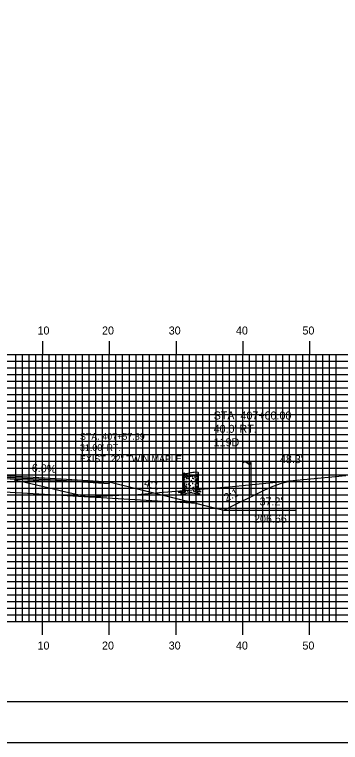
# Model space of a CAD drawing. Extents: x 852529 to 852872, y 364785 to 365005.
# Drawn here: x 852700.5 to 852749.3, y 364785.1 to 364894.2 of the extents above; entities that cross this region are included whole.
import ezdxf

# ---------------------------------------------------------------- set-up
doc = ezdxf.new("R2010")
doc.units = 0
for name, color, linetype in [('ANNOTATION', 7, 'Continuous'), ('BORDER', 7, 'Continuous'), ('D_Drainage_Text', 7, 'Continuous'), ('D_Roadway_Centerline', 7, 'Continuous'), ('D_Roadway_Edge_Shoulder', 7, 'Continuous'), ('D_Roadway_Edge_TW', 7, 'Continuous'), ('D_Roadway_Pavement', 7, 'Continuous'), ('D_Roadway_SlopeLines', 7, 'Continuous'), ('D_Roadway_SubGrade', 7, 'Continuous'), ('D_Text_Monospaced', 7, 'Continuous'), ('D_Text_Standard', 7, 'Continuous'), ('D_Utilities_Pole_Joint', 7, 'Continuous'), ('H_V ANNOTATION', 7, 'Continuous'), ('MAJOR', 7, 'Continuous'), ('MINOR', 7, 'Continuous'), ('PDRAIN', 7, 'Continuous'), ('PLOT BOUNDARY', 7, 'Continuous'), ('S_Roadway_Centerline', 7, 'Continuous'), ('S_Trees_Decid_Pay', 7, 'Continuous')]:
    doc.layers.add(name, color=color, linetype=linetype)

msp = doc.modelspace()

# ---------------------------------------------------------------- linework, layer by layer
at = {"layer": 'BORDER'}
msp.add_lwpolyline([(852545.13, 364791.23), (852865.13, 364791.23), (852865.13, 365001.23), (852545.13, 365001.23)], close=True, dxfattribs=at)
at = {"layer": 'D_Roadway_Centerline'}
msp.add_lwpolyline([(852662.11, 364822.74), (852662.73, 364822.94), (852663.86, 364823.23), (852674.73, 364825.94), (852682.73, 364826.1), (852694.73, 364825.38), (852706.73, 364824.66), (852714.73, 364824.18), (852727.89, 364820.89), (852731.89, 364819.89), (852738.01, 364822.95), (852739.26, 364823.52), (852740.51, 364823.95), (852741.76, 364824.26), (852743.01, 364824.45)], dxfattribs=at)
at = {"layer": 'D_Roadway_Edge_Shoulder'}
msp.add_lwpolyline([(852706.73, 364824.66), (852714.73, 364824.18), (852714.73, 364823.93), (852706.73, 364824.41)], close=True, dxfattribs=at)
at = {"layer": 'D_Roadway_Edge_TW'}
msp.add_lwpolyline([(852682.73, 364825.85), (852682.73, 364826.1), (852694.73, 364825.38), (852706.73, 364824.66), (852706.73, 364824.41), (852694.73, 364825.13)], close=True, dxfattribs=at)
at = {"layer": 'D_Roadway_Pavement'}
msp.add_lwpolyline([(852682.73, 364825.6), (852682.73, 364825.85), (852694.73, 364825.13), (852706.73, 364824.41), (852706.73, 364824.16), (852694.73, 364824.88)], close=True, dxfattribs=at)
at = {"layer": 'D_Roadway_SlopeLines'}
for points in [[(852714.73, 364824.18), (852731.89, 364819.89)], [(852731.89, 364819.89), (852738.01, 364822.95), (852739.26, 364823.52), (852740.51, 364823.95), (852741.76, 364824.26), (852743.01, 364824.45)]]:
    msp.add_lwpolyline(points, dxfattribs=at)
at = {"layer": 'D_Roadway_SubGrade'}
msp.add_lwpolyline([(852682.73, 364823.6), (852663.86, 364823.23), (852674.73, 364825.94), (852674.73, 364825.69), (852682.73, 364825.85), (852694.73, 364825.13), (852706.73, 364824.41), (852714.73, 364823.93), (852714.73, 364824.18), (852727.89, 364820.89), (852706.73, 364822.16), (852694.73, 364822.88)], close=True, dxfattribs=at)
at = {"layer": 'D_Utilities_Pole_Joint'}
for p, q in [((852734.73, 364826.99), (852734.89, 364827.1)), ((852734.73, 364822.23), (852734.73, 364826.99)), ((852735.2, 364827.1), (852735.36, 364826.99)), ((852735.51, 364827.1), (852735.36, 364826.99)), ((852735.36, 364826.99), (852735.51, 364826.88)), ((852735.98, 364826.99), (852735.82, 364827.1)), ((852735.82, 364826.88), (852735.98, 364826.99)), ((852735.98, 364822.23), (852735.98, 364826.99))]:
    msp.add_line(p, q, dxfattribs=at)
for centre, start, end in [((852735.04, 364826.88), 90, 125.2644), ((852735.04, 364826.88), 54.7356, 90), ((852735.67, 364826.88), 90, 125.2644), ((852735.67, 364827.1), 234.7356, 270), ((852735.67, 364826.88), 54.7356, 90), ((852735.67, 364827.1), 270, 305.2644)]:
    msp.add_arc(centre, 0.271, start, end, dxfattribs=at)
at = {"layer": 'MAJOR'}
for p, q in [((852704.73, 364845.24), (852704.73, 364843.23)), ((852714.73, 364845.24), (852714.73, 364843.23)), ((852724.73, 364845.24), (852724.73, 364843.23)), ((852734.73, 364845.24), (852734.73, 364843.23)), ((852744.73, 364845.24), (852744.73, 364843.23)), ((852554.73, 364843.23), (852834.73, 364843.23)), ((852554.73, 364843.23), (852834.73, 364843.23)), ((852704.73, 364803.23), (852704.73, 364843.23)), ((852714.73, 364803.23), (852714.73, 364843.23)), ((852724.73, 364803.23), (852724.73, 364843.23)), ((852734.73, 364803.23), (852734.73, 364843.23)), ((852744.73, 364803.23), (852744.73, 364843.23)), ((852554.73, 364838.23), (852834.73, 364838.23)), ((852554.73, 364833.23), (852834.73, 364833.23)), ((852554.73, 364828.23), (852834.73, 364828.23)), ((852554.73, 364823.23), (852834.73, 364823.23)), ((852554.73, 364818.23), (852834.73, 364818.23)), ((852554.73, 364813.23), (852834.73, 364813.23)), ((852554.73, 364808.23), (852834.73, 364808.23)), ((852554.73, 364803.23), (852834.73, 364803.23)), ((852554.73, 364803.23), (852834.73, 364803.23)), ((852704.73, 364801.23), (852704.73, 364803.23)), ((852714.73, 364801.23), (852714.73, 364803.23)), ((852724.73, 364801.23), (852724.73, 364803.23)), ((852734.73, 364801.23), (852734.73, 364803.23)), ((852744.73, 364801.23), (852744.73, 364803.23))]:
    msp.add_line(p, q, dxfattribs=at)
at = {"layer": 'MINOR'}
for p, q in [((852700.73, 364803.23), (852700.73, 364843.23)), ((852701.73, 364803.23), (852701.73, 364843.23)), ((852702.73, 364803.23), (852702.73, 364843.23)), ((852703.73, 364803.23), (852703.73, 364843.23)), ((852705.73, 364803.23), (852705.73, 364843.23)), ((852706.73, 364803.23), (852706.73, 364843.23)), ((852707.73, 364803.23), (852707.73, 364843.23)), ((852708.73, 364803.23), (852708.73, 364843.23)), ((852709.73, 364803.23), (852709.73, 364843.23)), ((852710.73, 364803.23), (852710.73, 364843.23)), ((852711.73, 364803.23), (852711.73, 364843.23)), ((852712.73, 364803.23), (852712.73, 364843.23)), ((852713.73, 364803.23), (852713.73, 364843.23)), ((852715.73, 364803.23), (852715.73, 364843.23)), ((852716.73, 364803.23), (852716.73, 364843.23)), ((852717.73, 364803.23), (852717.73, 364843.23)), ((852718.73, 364803.23), (852718.73, 364843.23)), ((852719.73, 364803.23), (852719.73, 364843.23)), ((852720.73, 364803.23), (852720.73, 364843.23)), ((852721.73, 364803.23), (852721.73, 364843.23)), ((852722.73, 364803.23), (852722.73, 364843.23)), ((852723.73, 364803.23), (852723.73, 364843.23)), ((852725.73, 364803.23), (852725.73, 364843.23)), ((852726.73, 364803.23), (852726.73, 364843.23)), ((852727.73, 364803.23), (852727.73, 364843.23)), ((852728.73, 364803.23), (852728.73, 364843.23)), ((852729.73, 364803.23), (852729.73, 364843.23)), ((852730.73, 364803.23), (852730.73, 364843.23)), ((852731.73, 364803.23), (852731.73, 364843.23)), ((852732.73, 364803.23), (852732.73, 364843.23)), ((852733.73, 364803.23), (852733.73, 364843.23)), ((852735.73, 364803.23), (852735.73, 364843.23)), ((852736.73, 364803.23), (852736.73, 364843.23)), ((852737.73, 364803.23), (852737.73, 364843.23)), ((852738.73, 364803.23), (852738.73, 364843.23)), ((852739.73, 364803.23), (852739.73, 364843.23)), ((852740.73, 364803.23), (852740.73, 364843.23)), ((852741.73, 364803.23), (852741.73, 364843.23)), ((852742.73, 364803.23), (852742.73, 364843.23)), ((852743.73, 364803.23), (852743.73, 364843.23)), ((852745.73, 364803.23), (852745.73, 364843.23)), ((852746.73, 364803.23), (852746.73, 364843.23)), ((852747.73, 364803.23), (852747.73, 364843.23)), ((852748.73, 364803.23), (852748.73, 364843.23)), ((852554.73, 364842.23), (852834.73, 364842.23)), ((852554.73, 364841.23), (852834.73, 364841.23)), ((852554.73, 364840.23), (852834.73, 364840.23)), ((852554.73, 364839.23), (852834.73, 364839.23)), ((852554.73, 364837.23), (852834.73, 364837.23)), ((852554.73, 364836.23), (852834.73, 364836.23)), ((852554.73, 364835.23), (852834.73, 364835.23)), ((852554.73, 364834.23), (852834.73, 364834.23)), ((852554.73, 364832.23), (852834.73, 364832.23)), ((852554.73, 364831.23), (852834.73, 364831.23)), ((852554.73, 364830.23), (852834.73, 364830.23)), ((852554.73, 364829.23), (852834.73, 364829.23)), ((852554.73, 364827.23), (852834.73, 364827.23)), ((852554.73, 364826.23), (852834.73, 364826.23)), ((852554.73, 364825.23), (852834.73, 364825.23)), ((852554.73, 364824.23), (852834.73, 364824.23)), ((852554.73, 364822.23), (852834.73, 364822.23)), ((852554.73, 364821.23), (852834.73, 364821.23)), ((852554.73, 364820.23), (852834.73, 364820.23)), ((852554.73, 364819.23), (852834.73, 364819.23)), ((852554.73, 364817.23), (852834.73, 364817.23)), ((852554.73, 364816.23), (852834.73, 364816.23)), ((852554.73, 364815.23), (852834.73, 364815.23)), ((852554.73, 364814.23), (852834.73, 364814.23)), ((852554.73, 364812.23), (852834.73, 364812.23)), ((852554.73, 364811.23), (852834.73, 364811.23)), ((852554.73, 364810.23), (852834.73, 364810.23)), ((852554.73, 364809.23), (852834.73, 364809.23)), ((852554.73, 364807.23), (852834.73, 364807.23)), ((852554.73, 364806.23), (852834.73, 364806.23)), ((852554.73, 364805.23), (852834.73, 364805.23)), ((852554.73, 364804.23), (852834.73, 364804.23))]:
    msp.add_line(p, q, dxfattribs=at)
at = {"layer": 'PDRAIN'}
msp.add_line((852731.89, 364819.89), (852742.66, 364819.89), dxfattribs=at)
at = {"layer": 'PLOT BOUNDARY'}
msp.add_lwpolyline([(852528.94, 364785.11), (852868.94, 364785.11), (852868.94, 365005.11), (852528.94, 365005.11)], close=True, dxfattribs=at)
at = {"layer": 'S_Roadway_Centerline'}
msp.add_lwpolyline([(852700.53, 364824.42), (852700.84, 364824.39), (852701.48, 364824.25), (852703.84, 364823.7), (852706.57, 364823.06), (852707.59, 364822.82), (852711.32, 364821.95), (852712.8, 364822.03), (852713.46, 364822.03), (852717.04, 364822.19), (852717.68, 364822.2), (852718.98, 364822.24), (852721.06, 364822.45), (852733.19, 364823.47), (852735.15, 364823.68), (852743.83, 364824.53), (852750.15, 364825.09)], dxfattribs=at)
at = {"layer": 'S_Trees_Decid_Pay'}
for p, q in [((852725.93, 364825.18), (852725.93, 364825)), ((852727.19, 364825.07), (852727.19, 364824.79)), ((852727.57, 364825.17), (852727.57, 364825.08)), ((852727.84, 364825.08), (852727.84, 364824.89)), ((852727.97, 364825.34), (852727.97, 364825.08)), ((852728.05, 364825.38), (852728.05, 364825.26)), ((852728.05, 364825.21), (852728.05, 364824.99)), ((852725.78, 364824.98), (852725.78, 364824.72)), ((852725.78, 364824.62), (852725.78, 364824.16)), ((852725.78, 364824.1), (852725.78, 364823.97)), ((852725.87, 364824.83), (852725.87, 364824.62)), ((852725.87, 364824.55), (852725.87, 364824.41)), ((852725.87, 364824.23), (852725.87, 364823.93)), ((852726.01, 364824.93), (852726.01, 364824.72)), ((852726.01, 364824.52), (852726.01, 364824.36)), ((852726.01, 364824), (852726.01, 364823.78)), ((852726.28, 364824.93), (852726.28, 364824.81)), ((852726.28, 364824.76), (852726.28, 364824.57)), ((852726.28, 364824.29), (852726.28, 364824.06)), ((852726.51, 364824.66), (852726.52, 364824.77)), ((852726.64, 364824.83), (852726.64, 364824.65)), ((852727.19, 364824.72), (852727.19, 364824.62)), ((852727.19, 364824.01), (852727.19, 364823.79)), ((852727.57, 364824.94), (852727.57, 364824.8)), ((852727.57, 364824.52), (852727.57, 364824.32)), ((852727.84, 364824.64), (852727.84, 364824.36)), ((852727.84, 364824.32), (852727.84, 364824.21)), ((852727.84, 364824.07), (852727.84, 364823.84)), ((852727.97, 364824.99), (852727.97, 364824.72)), ((852727.97, 364824.62), (852727.97, 364824.32)), ((852727.97, 364824.23), (852727.97, 364824.16)), ((852728.05, 364824.95), (852728.05, 364824.61)), ((852728.05, 364824.49), (852728.05, 364824.13)), ((852728.05, 364824.1), (852728.05, 364823.65)), ((852725.78, 364823.04), (852725.77, 364822.92)), ((852725.78, 364823.91), (852725.78, 364823.59)), ((852725.78, 364823.56), (852725.78, 364823.14)), ((852725.87, 364823.89), (852725.87, 364823.65)), ((852725.87, 364823.54), (852725.87, 364823.4)), ((852725.87, 364823.26), (852725.87, 364823.11)), ((852726.01, 364823.68), (852726.01, 364823.56)), ((852726.01, 364823.41), (852726.01, 364823.31)), ((852726.28, 364823.86), (852726.28, 364823.68)), ((852726.28, 364823.44), (852726.28, 364823.36)), ((852726.28, 364823.29), (852726.28, 364823.11)), ((852726.64, 364823.87), (852726.64, 364823.68)), ((852726.64, 364823.29), (852726.64, 364823.19)), ((852727.19, 364823.29), (852727.19, 364823.11)), ((852727.56, 364823.06), (852727.65, 364822.93)), ((852727.57, 364823.84), (852727.57, 364823.64)), ((852727.57, 364823.52), (852727.57, 364823.32)), ((852727.84, 364823.52), (852727.84, 364823.13)), ((852727.97, 364823.93), (852727.97, 364823.83)), ((852727.97, 364823.78), (852727.97, 364823.42)), ((852727.97, 364823.37), (852727.97, 364823.2)), ((852728.05, 364823.58), (852728.05, 364823.3))]:
    msp.add_line(p, q, dxfattribs=at)
for points in [[(852725.73, 364825.25), (852725.73, 364823.11), (852725.71, 364822.97), (852725.7, 364822.85), (852725.66, 364822.76), (852725.57, 364822.71), (852725.43, 364822.71), (852725.19, 364822.65), (852725.02, 364822.61), (852725.16, 364822.57), (852725.4, 364822.61), (852725.61, 364822.6), (852725.87, 364822.61), (852726, 364822.62), (852726.03, 364822.58), (852726.09, 364822.62), (852725.99, 364822.56), (852725.75, 364822.53), (852725.52, 364822.47), (852725.39, 364822.4), (852725.49, 364822.36), (852725.92, 364822.37), (852726.19, 364822.42), (852726.49, 364822.49), (852726.78, 364822.53), (852726.88, 364822.53), (852726.9, 364822.61), (852726.97, 364822.62), (852727.14, 364822.53), (852727.42, 364822.48), (852727.72, 364822.37), (852728.18, 364822.32), (852728.33, 364822.33), (852727.99, 364822.48), (852727.79, 364822.51), (852727.8, 364822.59), (852728.06, 364822.69), (852728.24, 364822.72), (852728.48, 364822.73), (852728.28, 364822.77), (852728.22, 364822.8), (852728.19, 364822.89), (852728.18, 364823.06), (852728.14, 364823.14), (852728.11, 364823.39), (852728.11, 364825.47)], [(852726.09, 364824.92), (852726.08, 364825.07), (852726.03, 364825.06), (852726.02, 364825.43), (852725.92, 364825.44), (852725.91, 364825.52), (852725.87, 364825.19), (852725.83, 364825.28), (852725.81, 364825.13), (852725.73, 364825.25), (852725.74, 364825.06)], [(852725.73, 364825.25), (852725.78, 364825.27), (852725.8, 364825.34), (852725.85, 364825.36), (852725.88, 364825.29)], [(852726.11, 364825.29), (852726.13, 364825.4), (852726.26, 364825.43), (852726.27, 364825.34)], [(852726.25, 364824.93), (852726.28, 364825.03), (852726.35, 364825.04), (852726.35, 364825.12), (852726.42, 364825.13), (852726.45, 364824.95)], [(852725.85, 364823.04), (852725.84, 364822.92), (852725.76, 364822.82)], [(852726, 364822.62), (852726.01, 364822.8), (852726.08, 364822.94), (852726.07, 364823.04)], [(852726.14, 364823.56), (852726.13, 364823.48), (852726.2, 364823.48), (852726.22, 364823.6)], [(852726.64, 364823.01), (852726.62, 364822.85), (852726.42, 364822.77), (852726.38, 364822.67)], [(852727.2, 364823), (852727.31, 364822.95), (852727.32, 364822.74), (852727.42, 364822.71)], [(852727.68, 364823.65), (852727.68, 364823.73), (852727.67, 364823.79)], [(852727.86, 364823.07), (852727.86, 364822.87), (852727.92, 364822.76), (852728.01, 364822.74)], [(852728, 364823.15), (852728.07, 364823.04), (852728.07, 364822.92)], [(852728.06, 364823.23), (852728.12, 364823.07), (852728.13, 364822.94), (852728.12, 364822.84)], [(852726.19, 364822.87), (852726.11, 364822.8), (852726.09, 364822.7), (852726.09, 364822.62)], [(852727.79, 364822.51), (852727.7, 364822.65), (852727.57, 364822.8)]]:
    msp.add_lwpolyline(points, dxfattribs=at)
for centre, radius, start, end in [((852726.54, 364824.06), 1.3, 107.8613, 113.3069), ((852728.02, 364819.47), 6.13, 100.7779, 107.8613), ((852728.02, 364819.47), 6.13, 93.6944, 100.7779), ((852725.82, 364831.04), 6.13, 280.7779, 287.8613), ((852727.71, 364824.29), 1.3, 78.2779, 93.6944), ((852727.3, 364826.44), 1.3, 287.8613, 303.2779), ((852727.88, 364825.09), 0.48, 69.9843, 78.2779), ((852727.75, 364825.76), 0.48, 303.2779, 311.5714), ((852727.98, 364825.39), 0.164, 55.7779, 69.9843), ((852727.97, 364825.21), 0.166, 301.67, 315), ((852727.96, 364825.52), 0.164, 311.5714, 325.7779), ((852728.02, 364825.43), 0.107, 45.9547, 55.7779), ((852728.04, 364825.46), 0.0645, 33.2779, 45.9547), ((852728, 364825.49), 0.107, 325.7779, 335.6011), ((852728.01, 364825.17), 0.109, 315, 324.8263), ((852728.05, 364825.47), 0.0544, 22.46, 33.2779), ((852728.06, 364825.47), 0.0467, 10.7779, 22.46), ((852728.04, 364825.47), 0.0645, 335.6011, 348.2779), ((852728.05, 364825.14), 0.0554, 337.5, 348.3185), ((852728.04, 364825.15), 0.0657, 324.8263, 337.5), ((852728.06, 364825.47), 0.0467, 359.0957, 10.7779), ((852728.05, 364825.47), 0.0544, 348.2779, 359.0957), ((852725.78, 364824.88), 0.0476, 180, 191.6815), ((852725.79, 364824.88), 0.0554, 191.6815, 202.5), ((852725.79, 364824.89), 0.0657, 202.5, 215.1737), ((852725.78, 364824.36), 0.0476, 180, 191.6815), ((852725.79, 364824.36), 0.0554, 191.6815, 202.5), ((852725.79, 364824.37), 0.0657, 202.5, 215.1737), ((852725.78, 364824.1), 0.0476, 180, 191.6815), ((852725.79, 364824.11), 0.0554, 191.6815, 202.5), ((852725.79, 364824.11), 0.0657, 202.5, 215.1737), ((852725.83, 364824.91), 0.109, 215.1737, 225), ((852725.83, 364824.39), 0.109, 215.1737, 225), ((852725.83, 364824.13), 0.109, 215.1737, 225), ((852725.87, 364824.95), 0.166, 225, 239.1924), ((852725.87, 364824.43), 0.166, 225, 239.1924), ((852725.87, 364824.18), 0.166, 225, 239.1924), ((852725.87, 364824.69), 0.166, 237.0378, 239.1924), ((852726.03, 364824.96), 0.484, 239.1924, 247.5), ((852726.03, 364824.71), 0.484, 239.1924, 245.7725), ((852726.34, 364825.71), 1.29, 247.5, 248.3537), ((852726.34, 364825.45), 1.29, 247.5, 248.4842), ((852726.34, 364825.19), 1.29, 247.5, 251.799), ((852726.34, 364825.97), 1.29, 250.6119, 255.2856), ((852726.34, 364825.71), 1.29, 255.2856, 259.2632), ((852726.13, 364826.22), 1.3, 268.1289, 273.6944), ((852726.34, 364825.45), 1.29, 261.8726, 262.8454), ((852726.92, 364830.04), 5.92, 262.8454, 263.7595), ((852725.82, 364831.04), 6.13, 273.6944, 274.0246), ((852725.82, 364831.04), 6.13, 275.9147, 280.7779), ((852726.92, 364830.56), 5.92, 266.0776, 267.3043), ((852726.92, 364830.3), 5.92, 270.1162, 271.7708), ((852726.92, 364830.56), 5.92, 273.5382, 274.8924), ((852726.92, 364830.82), 5.92, 274.9515, 276.3087), ((852726.92, 364830.3), 5.92, 276.3184, 277.1546), ((852727.49, 364825.71), 1.29, 277.1546, 278.3662), ((852727.49, 364825.45), 1.29, 279.2565, 285.6105), ((852727.5, 364826.23), 1.29, 285.5651, 289.0916), ((852727.49, 364825.19), 1.29, 285.6105, 290.1001), ((852727.49, 364825.97), 1.29, 288.0829, 292.5), ((852727.49, 364825.71), 1.29, 291.8071, 292.5), ((852727.8, 364824.96), 0.484, 292.5, 300.8076), ((852727.8, 364824.71), 0.484, 294.6372, 300.8076), ((852727.8, 364825.23), 0.484, 297.4162, 300.8076), ((852727.97, 364824.95), 0.166, 300.8076, 315), ((852727.97, 364824.69), 0.166, 300.8076, 301.6001), ((852727.97, 364824.43), 0.166, 300.8076, 315), ((852727.97, 364824.18), 0.166, 302.0694, 315), ((852728.01, 364824.91), 0.109, 315, 324.8263), ((852728.01, 364824.39), 0.109, 315, 324.8263), ((852728.01, 364824.13), 0.109, 315, 324.8263), ((852728.05, 364824.88), 0.0554, 337.5, 348.3185), ((852728.04, 364824.89), 0.0657, 324.8263, 337.5), ((852728.05, 364824.36), 0.0554, 337.5, 348.3185), ((852728.04, 364824.37), 0.0657, 324.8263, 337.5), ((852728.05, 364824.11), 0.0554, 337.5, 348.3185), ((852728.04, 364824.11), 0.0657, 324.8263, 337.5), ((852725.78, 364823.84), 0.0476, 180, 191.6815), ((852725.79, 364823.84), 0.0554, 191.6815, 202.5), ((852725.79, 364823.84), 0.0657, 202.5, 215.1737), ((852725.78, 364823.31), 0.0476, 180, 191.6815), ((852725.79, 364823.31), 0.0554, 191.6815, 202.5), ((852725.79, 364823.31), 0.0657, 202.5, 215.1737), ((852725.83, 364823.87), 0.109, 215.1737, 225), ((852725.83, 364823.34), 0.109, 215.1737, 225), ((852725.87, 364823.91), 0.166, 225, 239.1924), ((852725.87, 364823.38), 0.166, 225, 239.1924), ((852726.03, 364824.18), 0.484, 239.1924, 247.5), ((852726.03, 364823.65), 0.484, 239.1924, 247.5), ((852726.03, 364823.91), 0.484, 242.734, 247.5), ((852726.34, 364824.93), 1.29, 247.5, 248.3537), ((852726.34, 364824.4), 1.29, 247.5, 248.3537), ((852726.34, 364824.66), 1.29, 251.3664, 255.2856), ((852726.34, 364824.93), 1.29, 255.2856, 259.2463), ((852726.92, 364828.99), 5.92, 263.7831, 264.7656), ((852726.92, 364829.78), 5.92, 266.2721, 267.3043), ((852726.92, 364829.52), 5.92, 268.9207, 270), ((852726.92, 364829.52), 5.92, 270, 270.2757), ((852726.92, 364829.25), 5.92, 273.2637, 274.461), ((852726.92, 364829.52), 5.92, 276.3184, 277.1546), ((852726.92, 364829.25), 5.92, 276.3184, 277.1546), ((852727.49, 364824.93), 1.29, 277.1546, 278.3795), ((852727.49, 364824.66), 1.29, 277.1546, 278.3662), ((852727.49, 364824.66), 1.29, 285.6105, 289.1534), ((852727.5, 364824.4), 1.29, 291.3696, 292.0604), ((852727.8, 364824.18), 0.484, 292.5, 300.8076), ((852727.8, 364823.65), 0.484, 292.5, 296.5499), ((852727.97, 364823.91), 0.166, 300.8076, 302.0694), ((852727.97, 364823.64), 0.166, 302.0694, 315), ((852728.01, 364823.6), 0.109, 315, 324.8263), ((852728.05, 364823.84), 0.0554, 337.5, 348.3185), ((852728.05, 364823.57), 0.0554, 337.5, 348.3185), ((852728.04, 364823.57), 0.0657, 324.8263, 337.5)]:
    msp.add_arc(centre, radius, start, end, dxfattribs=at)

# ---------------------------------------------------------------- texts
at = {"layer": 'ANNOTATION'}
for s, rotation, p in [('-6.0%', 356.5664, (852702.56, 364825.72)), ('4:1', 345.9638, (852719.84, 364823.49)), ('2:1', 26.5651, (852732.25, 364821.16))]:
    msp.add_text(s, height=1.2, rotation=rotation, dxfattribs=at).set_placement(p)
for s, p in [("37.2'", (852737.23, 364820.62)), ('206.66', (852736.41, 364818.02))]:
    msp.add_text(s, height=1.2, dxfattribs=at).set_placement(p)
at = {"layer": 'D_Drainage_Text'}
for s, p in [('STA. 407+60.00', (852730.36, 364833.5)), ("40.0' RT.", (852730.36, 364831.5)), ('119D', (852730.36, 364829.49))]:
    msp.add_text(s, height=1.2, dxfattribs=at).set_placement(p)
at = {"layer": 'D_Text_Monospaced'}
for s, p in [('STA. 407+57.89', (852710.33, 364830.46)), ("31.00' RT.", (852710.33, 364828.79)), ('EXIST. 22" TWIN MAPLE', (852710.33, 364827.11))]:
    msp.add_text(s, height=1, dxfattribs=at).set_placement(p)
at = {"layer": 'D_Text_Standard'}
msp.add_text("48.3'", height=1.2, dxfattribs=at).set_placement((852740.29, 364826.96))
at = {"layer": 'H_V ANNOTATION'}
for s, p in [('10', (852703.98, 364846.23)), ('20', (852713.64, 364846.23)), ('30', (852723.63, 364846.23)), ('40', (852733.7, 364846.23)), ('50', (852743.66, 364846.23)), ('10', (852703.98, 364799.03)), ('20', (852713.64, 364799.03)), ('30', (852723.63, 364799.03)), ('40', (852733.7, 364799.03)), ('50', (852743.66, 364799.03))]:
    msp.add_text(s, height=1.2, dxfattribs=at).set_placement(p)

doc.saveas('drawing.dxf')
